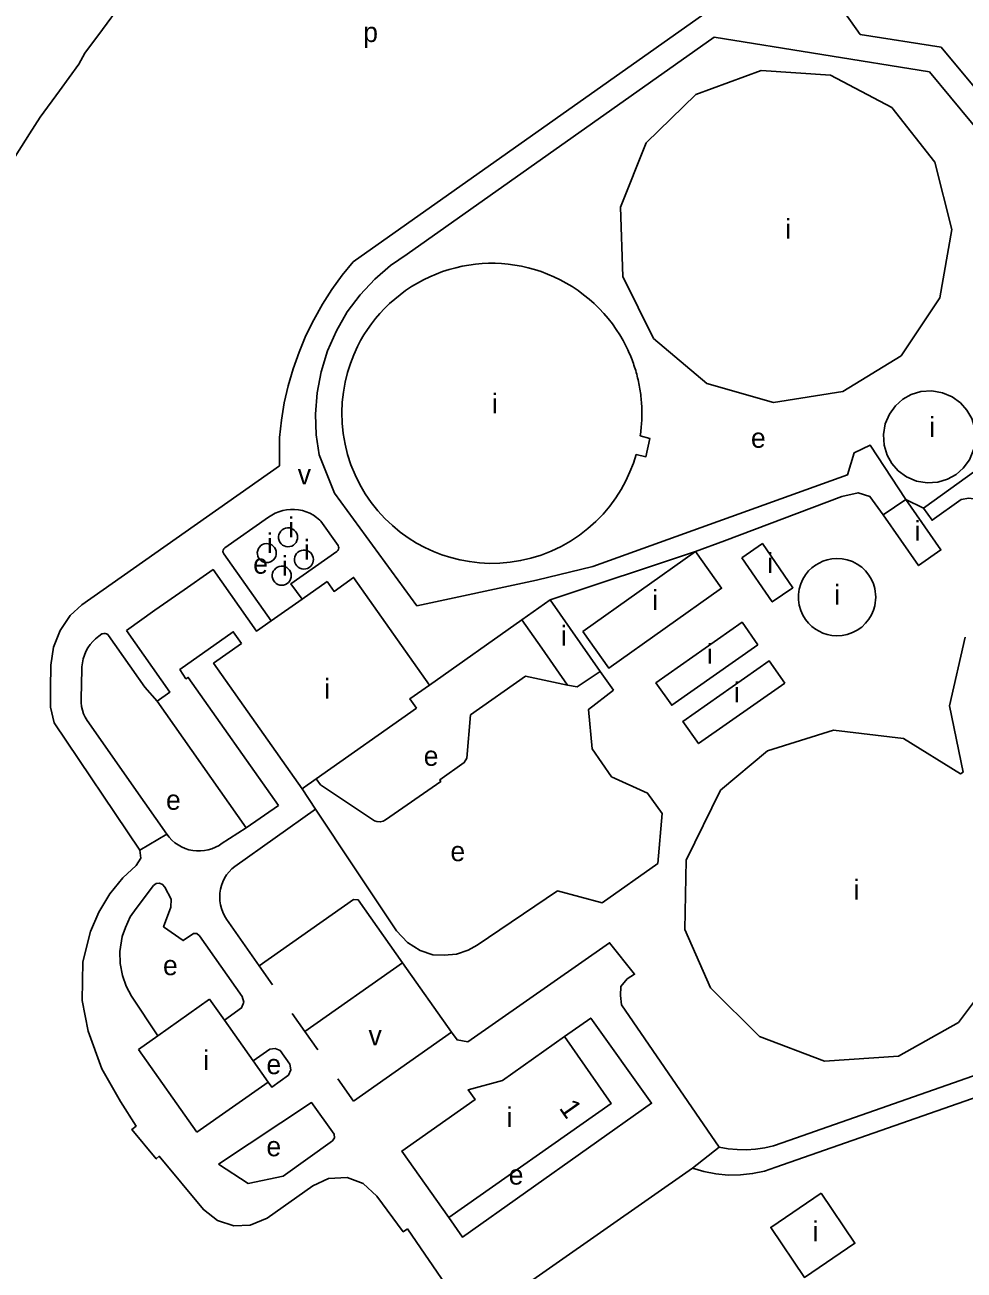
# Model space of a CAD drawing. Extents: x 162427 to 165104, y 384242 to 386287.
# Drawn here: x 162975.8 to 163165.4, y 385563.5 to 385814.9 of the extents above; entities that cross this region are included whole.
import ezdxf

# ---------------------------------------------------------------- set-up
doc = ezdxf.new("R2010")
doc.units = 0
for name, color, linetype in [('BLT_Basislijn', 7, 'Continuous'), ('BLT_Bebouwing', 7, 'Continuous'), ('BLT_Centroide', 7, 'Continuous'), ('BLT_Huisnummer', 7, 'Continuous'), ('BLT_Vlakafsluiter', 7, 'Continuous')]:
    doc.layers.add(name, color=color, linetype=linetype)

msp = doc.modelspace()

# ---------------------------------------------------------------- linework, layer by layer
at = {"layer": 'BLT_Basislijn'}
for p, q in [((163144.44, 385812.98), (163125.05, 385840.31)), ((163113.98, 385817.86), (163042.08, 385767.08)), ((163114.96, 385812.4), (163052.98, 385768.62)), ((163114.96, 385812.4), (163158.38, 385805.43)), ((163144.44, 385812.98), (163160.76, 385810.36)), ((163160.76, 385810.36), (163205.59, 385756.38)), ((163158.38, 385805.43), (163197.18, 385758.49)), ((163157.2, 385717.35), (163195.35, 385744.78)), ((163027.2, 385731.58), (163027.2, 385725.86)), ((163035.22, 385728.08), (163038.29, 385720.4)), ((163038.29, 385720.4), (163054.92, 385697.65)), ((163016.19, 385709.35), (163024.97, 385715.49)), ((163035.55, 385714.71), (163039.02, 385709.8)), ((163025.5, 385694.57), (163015.96, 385708.13)), ((163081.81, 385698.82), (163111.19, 385708.56)), ((163090.43, 385705.58), (163079.09, 385702.82)), ((163054.92, 385697.65), (163079.09, 385702.82)), ((163076.14, 385694.81), (163057.48, 385681.6)), ((162991.37, 385691.94), (162990.72, 385691.49)), ((163000, 385681.24), (162992.72, 385691.61)), ((162987.32, 385684.86), (162987.14, 385678.85)), ((163091.92, 385684.4), (163094.62, 385680.57)), ((163002.52, 385678.41), (163000, 385681.24)), ((162988.37, 385674.46), (163000, 385657.89)), ((163031.75, 385660.68), (163034.5, 385656.55)), ((163000, 385657.89), (163004.47, 385651.53)), ((163034.5, 385656.55), (163018.16, 385645.04)), ((163034.5, 385656.55), (163042.22, 385644.95)), ((163015.42, 385649.56), (163020.49, 385652.82)), ((163042.22, 385644.95), (163050.81, 385632.05)), ((163023.11, 385624.99), (163025.82, 385621.12)), ((163032.32, 385611.67), (163052.05, 385625.59)), ((163052.05, 385625.59), (163061.95, 385611.56)), ((163029.74, 385615.35), (163032.32, 385611.67)), ((163032.32, 385611.67), (163034.91, 385607.98)), ((163042.14, 385597.66), (163061.95, 385611.56)), ((163128.68, 385589.2), (163171.99, 385604.44)), ((163038.98, 385602.17), (163042.14, 385597.66)), ((163127.4, 385584.29), (163172.8, 385600.2)), ((163074.07, 385558.59), (163110.58, 385584.14))]:
    msp.add_line(p, q, dxfattribs=at)
for points in [[(162986.73, 385806.97), (162987.92, 385809.21), (162991.49, 385813.99), (162995.07, 385818.77), (162995.6, 385819.85), (162997.8, 385822.92), (163000, 385826), (163003.85, 385832.01)], [(162967.19, 385774.18), (162968, 385777.03), (162969.52, 385780.12), (162970.38, 385782.22), (162971.21, 385783.41), (162973.07, 385787.02), (162976.73, 385792.87), (162978.92, 385796.24), (162982.82, 385801.61), (162986.73, 385806.97)], [(163052.98, 385768.62), (163049.61, 385766.3), (163046.43, 385763.57), (163043.5, 385760.43), (163040.89, 385756.94), (163038.68, 385753.13), (163036.91, 385749.09), (163035.61, 385744.88), (163034.81, 385740.6), (163034.49, 385736.32), (163034.64, 385732.12), (163035.22, 385728.08)], [(163042.08, 385767.08), (163039.86, 385764.36), (163037.78, 385761.49), (163035.86, 385758.5), (163034.11, 385755.38), (163032.53, 385752.16), (163031.15, 385748.85), (163029.95, 385745.47), (163028.96, 385742.04), (163028.17, 385738.57), (163027.58, 385735.07), (163027.2, 385731.58)], [(163164.83, 385719.12), (163166.35, 385719.35), (163167.81, 385719.16), (163168.98, 385718.52), (163170.02, 385717.48), (163176.84, 385708.15), (163180.05, 385710.56), (163174.91, 385717.45), (163177.13, 385719.11), (163176.46, 385720.46), (163176.42, 385722.43), (163177.06, 385724.12), (163178.25, 385725.83), (163180.18, 385727.13), (163183.32, 385722.66), (163186.42, 385724.82), (163181.97, 385731.38)], [(163090.43, 385705.58), (163141.87, 385724.08), (163143.17, 385728.54), (163146.46, 385730.03), (163153.6, 385719.12)], [(163027.2, 385725.86), (162987.34, 385697.83), (162984.98, 385695.66), (162982.92, 385692.64), (162981.58, 385689.3), (162981.08, 385685.67), (162980.97, 385680.87), (162980.97, 385677.19), (162981.69, 385674.01), (162999, 385648.3)], [(163149.08, 385715.96), (163146.38, 385719.7), (163143.99, 385720.45), (163140.68, 385719.72), (163117.03, 385710.77), (163111.19, 385708.56)], [(163164.83, 385719.12), (163158.93, 385714.9), (163157.2, 385717.35)], [(163024.97, 385715.49), (163025.64, 385715.94), (163026.34, 385716.32), (163027.08, 385716.63), (163027.85, 385716.86), (163028.64, 385717.02), (163029.44, 385717.1), (163030.24, 385717.09), (163031.04, 385717.01), (163031.83, 385716.85), (163032.6, 385716.61), (163033.33, 385716.3), (163034.04, 385715.91), (163034.7, 385715.46), (163035.32, 385714.94), (163035.55, 385714.71)], [(163015.96, 385708.13), (163015.84, 385708.36), (163015.8, 385708.62), (163015.84, 385708.89), (163015.96, 385709.12), (163016.19, 385709.35)], [(163038.76, 385708.56), (163029.51, 385702.09), (163031.79, 385698.95)], [(163039.02, 385709.8), (163039.13, 385709.56), (163039.17, 385709.3), (163039.13, 385709.04), (163039.01, 385708.8), (163038.76, 385708.56)], [(162990.72, 385691.49), (162990.09, 385690.99), (162989.51, 385690.42), (162988.99, 385689.8), (162988.53, 385689.13), (162988.14, 385688.42), (162987.82, 385687.68), (162987.58, 385686.9), (162987.42, 385686.11), (162987.33, 385685.3), (162987.32, 385684.86)], [(162992.72, 385691.61), (162992.54, 385691.83), (162992.3, 385691.98), (162992.03, 385692.06), (162991.75, 385692.07), (162991.48, 385691.99), (162991.37, 385691.94)], [(163034.6, 385662.73), (163035.5, 385661.46), (163046.35, 385654.22), (163046.86, 385654.06), (163047.53, 385654.01), (163048.1, 385654.15), (163048.62, 385654.45), (163059.74, 385662.18), (163059.55, 385662.48), (163064.51, 385665.97), (163065.05, 385666.86), (163065.76, 385675.6), (163076.88, 385683.43)], [(163076.88, 385683.43), (163085.35, 385681.61)], [(163094.62, 385680.57), (163089.58, 385676.71), (163090.29, 385668.75), (163094.23, 385663.12), (163101.5, 385659.81), (163104.42, 385655.68), (163103.54, 385645.63)], [(162987.14, 385678.85), (162987.15, 385678.08), (162987.24, 385677.31), (162987.41, 385676.56), (162987.66, 385675.83), (162987.98, 385675.13), (162988.37, 385674.46)], [(163004.47, 385651.53), (163004.95, 385650.9), (163005.49, 385650.33), (163006.09, 385649.81), (163006.74, 385649.35), (163007.42, 385648.96), (163008.15, 385648.64), (163008.9, 385648.4), (163009.68, 385648.24), (163010.46, 385648.15), (163011.26, 385648.14), (163012.05, 385648.22), (163012.82, 385648.37), (163013.58, 385648.6), (163014.31, 385648.91), (163015.01, 385649.28), (163015.42, 385649.56)], [(162999, 385648.3), (162999.23, 385646.71), (162998.25, 385645.24), (162995.61, 385642.71), (162992.97, 385639.47), (162990.71, 385635.77), (162989.06, 385631.9), (162987.5, 385625.75), (162987.36, 385617.93), (162988.59, 385611.79), (162991.36, 385604.18), (162995.11, 385597.6), (162998.27, 385592.61), (162997.38, 385591.89), (163002.34, 385585.99), (163002.95, 385586.51), (163011.86, 385575.74), (163014.69, 385573.53), (163017.98, 385572.49), (163021.31, 385572.6), (163024.74, 385574.01), (163033.93, 385580.54), (163037.08, 385582.06), (163040.85, 385582.25), (163044.11, 385581.05), (163046.88, 385578.45), (163052.18, 385571.27), (163053.01, 385571.86)], [(163083.35, 385640.11), (163092.35, 385637.7), (163103.54, 385645.63)], [(163018.16, 385645.04), (163017.56, 385644.52), (163017.02, 385643.94), (163016.54, 385643.32), (163016.12, 385642.64), (163015.77, 385641.93), (163015.5, 385641.19), (163015.3, 385640.42), (163015.18, 385639.64), (163015.14, 385638.84), (163015.18, 385638.05), (163015.3, 385637.27), (163015.49, 385636.5), (163015.77, 385635.76), (163016.12, 385635.04), (163016.53, 385634.37), (163023.11, 385624.99)], [(163002.64, 385610.81), (162997.36, 385618.85), (162996.27, 385620.86), (162995.5, 385622.98), (162995.03, 385625.44), (162994.97, 385627.85), (162995.44, 385630.89), (162996.13, 385632.67), (162997.09, 385634.83), (162998.29, 385636.55), (163001.79, 385641.16), (163002.34, 385641.55), (163003, 385641.62), (163003.59, 385641.4), (163004.06, 385640.87), (163005.33, 385638.44), (163005.26, 385636.77), (163003.82, 385632.85), (163007.76, 385630.07), (163009.82, 385631.49), (163010.53, 385631.49), (163011.04, 385630.99), (163019.68, 385618.75), (163020, 385617.59), (163019.55, 385616.46), (163016.08, 385614)], [(163050.81, 385632.05), (163053.01, 385629.68), (163055.61, 385628.06), (163058.15, 385627.2), (163060.46, 385627.08), (163062.95, 385627.31), (163065.26, 385628.12), (163067.08, 385629.12), (163083.35, 385640.11)], [(163023.11, 385624.99), (163042.17, 385638.36), (163043.1, 385638.27), (163052.05, 385625.59)], [(163061.95, 385611.56), (163063.05, 385610.01), (163065.25, 385609.6), (163093.83, 385629.62), (163098.88, 385623.27), (163097.39, 385622.34), (163096.09, 385620.78), (163096.03, 385618.97), (163096.25, 385617.08), (163115.97, 385588.35)], [(163084.75, 385610.66), (163090.02, 385614.42), (163102.31, 385597.21), (163064.12, 385570.22), (163061.37, 385574.14)], [(163021.89, 385605.79), (163025.28, 385608.14), (163026.34, 385608.29), (163027.32, 385607.86), (163029.27, 385605.13), (163029.51, 385603.98), (163029.03, 385602.91), (163025.69, 385600.46), (163024.93, 385601.5)], [(163128.68, 385589.2), (163126.94, 385588.65), (163125.14, 385588.23), (163123.31, 385587.96), (163121.46, 385587.84), (163119.61, 385587.86), (163117.77, 385588.03), (163115.97, 385588.35)], [(163110.58, 385584.14), (163112.89, 385583.43), (163115.3, 385582.95), (163117.76, 385582.71), (163120.25, 385582.74), (163122.7, 385583.01), (163125.1, 385583.54), (163127.4, 385584.29)], [(163053.01, 385571.86), (163069.39, 385548), (163103.5, 385500), (163138.29, 385450.78), (163142.13, 385444.88), (163144.53, 385439.97), (163145.57, 385436.28), (163145.97, 385432.21), (163145.34, 385429.37)]]:
    msp.add_lwpolyline(points, dxfattribs=at)
msp.add_lwpolyline([(163014.87, 385584.9), (163033.69, 385597.34), (163038.22, 385591), (163038.3, 385590.27), (163037.93, 385589.64), (163027.93, 385582.52), (163020.91, 385581.04)], close=True, dxfattribs=at)
at = {"layer": 'BLT_Bebouwing'}
for p, q in [((163149.08, 385715.96), (163153.6, 385719.12)), ((163088.46, 385692.43), (163111.19, 385708.56)), ((163036.82, 385702.51), (163031.79, 385698.95)), ((163031.79, 385698.95), (163025.5, 385694.57)), ((163020.49, 385652.82), (163002.52, 385678.41)), ((163034.6, 385662.73), (163054.89, 385676.94)), ((163020.49, 385652.82), (163026.99, 385657.33)), ((163002.64, 385610.81), (163013.09, 385618.22)), ((163013.09, 385618.22), (163016.08, 385614)), ((163016.08, 385614), (163021.89, 385605.79)), ((162998.77, 385608.07), (163002.64, 385610.81)), ((163010.51, 385591.35), (162998.77, 385608.07)), ((163021.89, 385605.79), (163024.93, 385601.5)), ((163024.93, 385601.5), (163010.51, 385591.35))]:
    msp.add_line(p, q, dxfattribs=at)
for points in [[(163111.27, 385800.87), (163124.41, 385805.66)], [(163124.41, 385805.66), (163138.42, 385804.77)], [(163138.42, 385804.77), (163150.78, 385798.24)], [(163101.23, 385791.1), (163111.27, 385800.87)], [(163150.78, 385798.24), (163159.47, 385787.17)], [(163096.01, 385778.08), (163101.23, 385791.1)], [(163159.47, 385787.17), (163162.91, 385773.62)], [(163096.52, 385764.1), (163096.01, 385778.08)], [(163162.91, 385773.62), (163160.51, 385759.82)], [(163097.17, 385750), (163096.56, 385751.16), (163095.9, 385752.3), (163095.17, 385753.43), (163094.39, 385754.53), (163093.56, 385755.6), (163092.67, 385756.65), (163091.72, 385757.65), (163090.73, 385758.63), (163089.69, 385759.55), (163088.6, 385760.43), (163087.47, 385761.27), (163086.3, 385762.05), (163085.1, 385762.77), (163083.86, 385763.44), (163082.6, 385764.05), (163081.32, 385764.6), (163080.01, 385765.09), (163078.69, 385765.51), (163077.37, 385765.87), (163076.03, 385766.17), (163074.7, 385766.41), (163073.37, 385766.58), (163072.04, 385766.7), (163070.73, 385766.76), (163069.42, 385766.76), (163068.11, 385766.7), (163066.78, 385766.58), (163065.45, 385766.41), (163064.11, 385766.17), (163062.78, 385765.87), (163061.45, 385765.51), (163060.13, 385765.09), (163058.83, 385764.6), (163057.54, 385764.05), (163056.28, 385763.44), (163055.05, 385762.77), (163053.84, 385762.05), (163052.67, 385761.27), (163051.55, 385760.43), (163050.46, 385759.55), (163049.42, 385758.63), (163048.42, 385757.65), (163047.48, 385756.65), (163046.59, 385755.6), (163045.75, 385754.53), (163044.97, 385753.43), (163044.25, 385752.3), (163043.58, 385751.16), (163042.98, 385750)], [(163102.68, 385751.61), (163096.52, 385764.1)], [(163160.51, 385759.82), (163152.68, 385748.11)], [(163113.48, 385742.49), (163102.68, 385751.61)], [(163042.98, 385750), (163042.2, 385748.32), (163041.51, 385746.55), (163040.93, 385744.7), (163040.45, 385742.77), (163040.1, 385740.78), (163039.87, 385738.73), (163039.79, 385736.64), (163039.85, 385734.52), (163040.07, 385732.39), (163040.44, 385730.26), (163040.96, 385728.15), (163041.63, 385726.07), (163042.46, 385724.05), (163043.42, 385722.1), (163044.52, 385720.23), (163045.74, 385718.46), (163047.07, 385716.79), (163048.49, 385715.24), (163050, 385713.81), (163051.57, 385712.5), (163053.2, 385711.33), (163054.87, 385710.29), (163056.56, 385709.38), (163058.26, 385708.6), (163059.97, 385707.93), (163061.76, 385707.36), (163063.62, 385706.89), (163065.55, 385706.54), (163067.55, 385706.3), (163069.59, 385706.2), (163071.66, 385706.24), (163073.76, 385706.42), (163075.87, 385706.76), (163077.96, 385707.24), (163080.04, 385707.88), (163082.07, 385708.67), (163084.04, 385709.61), (163085.94, 385710.68), (163087.75, 385711.89), (163089.45, 385713.21), (163091.05, 385714.64), (163092.53, 385716.16), (163093.88, 385717.76), (163095.1, 385719.42), (163096.18, 385721.13), (163097.13, 385722.87), (163097.95, 385724.64), (163098.63, 385726.41), (163099.2, 385728.17)], [(163100.02, 385731.96), (163100.07, 385732.33), (163100.12, 385732.7), (163100.17, 385733.08), (163100.21, 385733.45), (163100.24, 385733.82), (163100.27, 385734.2), (163100.3, 385734.57), (163100.32, 385734.95), (163100.34, 385735.33), (163100.35, 385735.71), (163100.35, 385736.08), (163100.36, 385736.46), (163100.36, 385736.84), (163100.35, 385737.22), (163100.34, 385737.6), (163100.32, 385737.98), (163100.3, 385738.36), (163100.27, 385738.74), (163100.24, 385739.12), (163100.21, 385739.5), (163100.17, 385739.88), (163100.12, 385740.26), (163100.07, 385740.64), (163100.02, 385741.01), (163099.96, 385741.39), (163099.89, 385741.77), (163099.82, 385742.14), (163099.75, 385742.52), (163099.67, 385742.89), (163099.59, 385743.26), (163099.5, 385743.63), (163099.41, 385744), (163099.31, 385744.37), (163099.21, 385744.74), (163099.1, 385745.1), (163098.99, 385745.46), (163098.88, 385745.83), (163098.76, 385746.18), (163098.64, 385746.54), (163098.51, 385746.9), (163098.38, 385747.25), (163098.24, 385747.6), (163098.1, 385747.95), (163097.96, 385748.3), (163097.81, 385748.65), (163097.65, 385748.99), (163097.5, 385749.33), (163097.34, 385749.67), (163097.17, 385750)], [(163152.68, 385748.11), (163140.89, 385740.88)], [(163126.91, 385738.68), (163113.48, 385742.49)], [(163140.89, 385740.88), (163126.91, 385738.68)], [(163163.76, 385724.14), (163165.23, 385725.43), (163166.45, 385727.11), (163167.3, 385729.1), (163167.67, 385731.26), (163167.53, 385733.42), (163166.92, 385735.41), (163165.97, 385737.11), (163164.68, 385738.57), (163163, 385739.8), (163161.01, 385740.65), (163158.85, 385741.01), (163156.69, 385740.87), (163154.7, 385740.26), (163153, 385739.31)], [(163153, 385739.31), (163151.54, 385738.02), (163150.31, 385736.34), (163149.46, 385734.35), (163149.09, 385732.19), (163149.24, 385730.03), (163149.84, 385728.04), (163150.8, 385726.34), (163152.09, 385724.88), (163153.76, 385723.65), (163155.75, 385722.8), (163157.92, 385722.44), (163160.08, 385722.58), (163162.06, 385723.18), (163163.76, 385724.14)], [(163100.02, 385731.96), (163101.93, 385731.42), (163101.15, 385727.72), (163099.2, 385728.17)], [(163153.6, 385719.12), (163160.72, 385708.92), (163156.2, 385705.76), (163149.08, 385715.96)], [(163030.85, 385711.46), (163030.81, 385711.85), (163030.69, 385712.22), (163030.5, 385712.56), (163030.25, 385712.86), (163029.93, 385713.09), (163029.58, 385713.26), (163029.2, 385713.36), (163028.81, 385713.37), (163028.43, 385713.31), (163028.06, 385713.17), (163027.73, 385712.96), (163027.45, 385712.68), (163027.24, 385712.36), (163027.09, 385711.99), (163027.02, 385711.61), (163027.03, 385711.22), (163027.12, 385710.84), (163027.28, 385710.48), (163027.51, 385710.17), (163027.8, 385709.9), (163028.14, 385709.71), (163028.51, 385709.58), (163028.9, 385709.54), (163029.29, 385709.57), (163029.67, 385709.68), (163030.01, 385709.87), (163030.31, 385710.12), (163030.55, 385710.43), (163030.73, 385710.78), (163030.83, 385711.16), (163030.85, 385711.46)], [(163026.56, 385708.27), (163026.52, 385708.66), (163026.4, 385709.03), (163026.21, 385709.37), (163025.96, 385709.67), (163025.64, 385709.91), (163025.29, 385710.08), (163024.91, 385710.17), (163024.52, 385710.18), (163024.13, 385710.12), (163023.77, 385709.98), (163023.44, 385709.77), (163023.16, 385709.49), (163022.94, 385709.17), (163022.8, 385708.8), (163022.73, 385708.42), (163022.74, 385708.03), (163022.82, 385707.65), (163022.99, 385707.29), (163023.22, 385706.98), (163023.51, 385706.72), (163023.85, 385706.52), (163024.22, 385706.4), (163024.61, 385706.35), (163025, 385706.38), (163025.38, 385706.49), (163025.72, 385706.68), (163026.02, 385706.93), (163026.26, 385707.24), (163026.44, 385707.59), (163026.54, 385707.97), (163026.56, 385708.27)], [(163034.05, 385706.96), (163034.01, 385707.35), (163033.89, 385707.72), (163033.7, 385708.06), (163033.44, 385708.36), (163033.13, 385708.6), (163032.78, 385708.77), (163032.4, 385708.86), (163032.01, 385708.88), (163031.62, 385708.81), (163031.26, 385708.67), (163030.93, 385708.46), (163030.65, 385708.18), (163030.43, 385707.86), (163030.29, 385707.49), (163030.21, 385707.11), (163030.22, 385706.72), (163030.31, 385706.34), (163030.48, 385705.98), (163030.71, 385705.67), (163031, 385705.41), (163031.34, 385705.21), (163031.71, 385705.09), (163032.1, 385705.04), (163032.49, 385705.07), (163032.86, 385705.19), (163033.21, 385705.37), (163033.51, 385705.62), (163033.75, 385705.93), (163033.93, 385706.28), (163034.02, 385706.66), (163034.05, 385706.96)], [(163111.19, 385708.56), (163116.44, 385701.17), (163093.71, 385685.04), (163088.46, 385692.43)], [(163120.51, 385707.28), (163124.69, 385710.18), (163130.84, 385701.29), (163126.66, 385698.4), (163120.51, 385707.28)], [(163029.58, 385703.7), (163029.54, 385704.09), (163029.42, 385704.46), (163029.23, 385704.8), (163028.97, 385705.1), (163028.66, 385705.34), (163028.31, 385705.5), (163027.93, 385705.6), (163027.54, 385705.61), (163027.15, 385705.55), (163026.79, 385705.41), (163026.46, 385705.2), (163026.18, 385704.92), (163025.96, 385704.6), (163025.81, 385704.23), (163025.74, 385703.85), (163025.75, 385703.46), (163025.84, 385703.08), (163026, 385702.72), (163026.24, 385702.41), (163026.53, 385702.14), (163026.87, 385701.95), (163027.24, 385701.82), (163027.63, 385701.78), (163028.02, 385701.81), (163028.39, 385701.92), (163028.74, 385702.11), (163029.04, 385702.36), (163029.28, 385702.67), (163029.45, 385703.02), (163029.55, 385703.4), (163029.58, 385703.7)], [(163139.71, 385691.58), (163138.71, 385691.65), (163137.76, 385691.84), (163136.89, 385692.12), (163135.38, 385692.92), (163134.67, 385693.46), (163134, 385694.11), (163133.39, 385694.87), (163132.85, 385695.74), (163132.43, 385696.71), (163132.13, 385697.75), (163131.97, 385698.83), (163131.97, 385699.93), (163132.13, 385701.02), (163132.43, 385702.06), (163132.85, 385703.02), (163133.39, 385703.89), (163134, 385704.66), (163134.67, 385705.31), (163135.38, 385705.84), (163136.89, 385706.64), (163137.76, 385706.93), (163138.71, 385707.12), (163139.71, 385707.19), (163140.76, 385707.12), (163141.81, 385706.91), (163142.84, 385706.55), (163143.82, 385706.05), (163144.72, 385705.41), (163145.51, 385704.66), (163146.17, 385703.83), (163146.7, 385702.95), (163147.1, 385702.04), (163147.37, 385701.12), (163147.56, 385699.38), (163147.37, 385697.64), (163147.1, 385696.73), (163146.7, 385695.82), (163146.17, 385694.93), (163145.51, 385694.1), (163144.72, 385693.35), (163143.82, 385692.72), (163142.84, 385692.21), (163141.81, 385691.85), (163140.76, 385691.64), (163139.71, 385691.58)], [(163025.5, 385694.57), (163022.59, 385692.51), (163013.81, 385704.95), (163013.13, 385704.51), (163007.98, 385700.86), (163002.03, 385696.72), (162996.34, 385692.64)], [(163057.48, 385681.6), (163042.16, 385703.35), (163038.23, 385700.55), (163036.82, 385702.51)], [(163076.14, 385694.81), (163081.81, 385698.82)], [(163081.81, 385698.82), (163091.92, 385684.4)], [(163085.35, 385681.61), (163080.16, 385689.06), (163076.14, 385694.81)], [(163123.75, 385689.78), (163120.58, 385694.3), (163103.19, 385682.07), (163106.37, 385677.56), (163123.75, 385689.78)], [(163002.52, 385678.41), (163005.09, 385680.21), (162996.34, 385692.64)], [(163026.99, 385657.33), (163008.8, 385683.18), (163008.33, 385682.92), (163007.12, 385684.74), (163017.88, 385692.38), (163019.54, 385690.02)], [(163162.42, 385677.41), (163165.6, 385691.3)], [(163019.54, 385690.02), (163013.9, 385686.05), (163031.75, 385660.68)], [(163129.19, 385682.02), (163126.05, 385686.5), (163108.65, 385674.29), (163111.8, 385669.81), (163129.19, 385682.02)], [(163091.92, 385684.4), (163087.3, 385681.26), (163085.35, 385681.61)], [(163054.89, 385676.94), (163053.52, 385678.86), (163057.48, 385681.6)], [(163153.17, 385670.86), (163164.66, 385663.74), (163165.18, 385664.08), (163162.42, 385677.41)], [(163125.7, 385668.34), (163139.06, 385672.5)], [(163139.06, 385672.5), (163153.17, 385670.86)], [(163116.19, 385660.4), (163125.7, 385668.34)], [(163031.75, 385660.68), (163033.08, 385661.64), (163033.17, 385661.7), (163034.6, 385662.73)], [(163109.32, 385646.31), (163116.19, 385660.4)], [(163109.02, 385632.28), (163109.32, 385646.31)], [(163114.18, 385620.49), (163109.02, 385632.28)], [(163172.72, 385624.79), (163164.29, 385613.54)], [(163124.06, 385610.66), (163114.18, 385620.49)], [(163164.29, 385613.54), (163152.12, 385606.7)], [(163061.37, 385574.14), (163051.92, 385587.58), (163066.71, 385597.98), (163065.31, 385599.96), (163072.2, 385601.84), (163084.75, 385610.66)], [(163084.75, 385610.66), (163094.16, 385597.2), (163061.37, 385574.14)], [(163137.2, 385605.74), (163124.06, 385610.66)], [(163152.12, 385606.7), (163137.2, 385605.74)]]:
    msp.add_lwpolyline(points, dxfattribs=at)
msp.add_lwpolyline([(163136.54, 385579.04), (163143.36, 385568.96), (163133.17, 385562.07), (163126.35, 385572.15)], close=True, dxfattribs=at)
at = {"layer": 'BLT_Vlakafsluiter'}
for p, q in [((163157.2, 385717.35), (163153.6, 385719.12)), ((162999, 385648.3), (163004.47, 385651.53)), ((163110.58, 385584.14), (163115.97, 385588.35))]:
    msp.add_line(p, q, dxfattribs=at)

# ---------------------------------------------------------------- texts
at = {"layer": 'BLT_Centroide'}
for s, p in [('p', (163044.11, 385811.43)), ('i', (163129.29, 385771.72)), ('i', (163070.08, 385736.47)), ('i', (163158.38, 385731.72)), ('e', (163122.37, 385729.53)), ('v', (163030.89, 385722.17)), ('i', (163028.94, 385711.47)), ('i', (163155.37, 385710.75)), ('i', (163024.64, 385708.27)), ('i', (163032.12, 385706.95)), ('i', (163125.67, 385704.28)), ('e', (163021.9, 385704.11)), ('i', (163027.66, 385703.69)), ('i', (163102.45, 385696.81)), ('i', (163139.17, 385697.86)), ('i', (163084.03, 385689.58)), ('i', (163113.47, 385685.94)), ('i', (163036.25, 385678.88)), ('i', (163118.92, 385678.16)), ('e', (163056.32, 385665.33)), ('e', (163004.3, 385656.46)), ('e', (163061.71, 385646.08)), ('i', (163143.05, 385638.34)), ('e', (163003.69, 385623.07)), ('v', (163045.18, 385608.94)), ('i', (163011.84, 385603.91)), ('e', (163024.57, 385603.09)), ('i', (163073.05, 385592.41)), ('e', (163024.57, 385586.52)), ('e', (163073.47, 385580.8)), ('i', (163134.78, 385569.36))]:
    msp.add_text(s, height=4, dxfattribs=at).set_placement(p)
at = {"layer": 'BLT_Huisnummer'}
msp.add_text('1', height=4, rotation=305.1812, dxfattribs=at).set_placement((163083.53, 385596.23))

doc.saveas('drawing.dxf')
